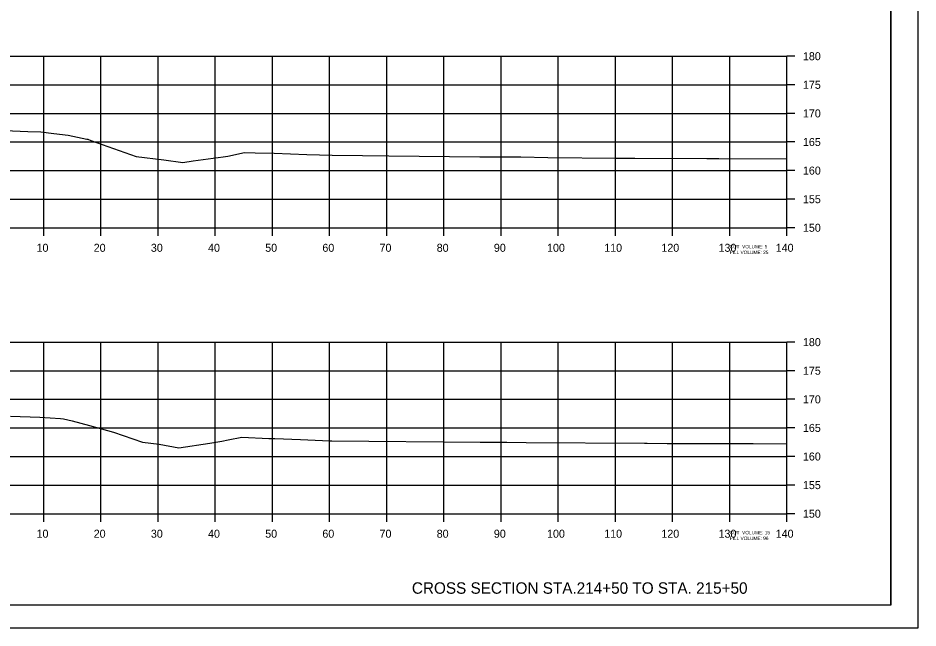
# Model space of a CAD drawing. Extents: x 1368503 to 1373085, y 379840 to 381833.
# Drawn here: x 1368678.6 to 1368836, y 381406.1 to 381512.7 of the extents above; entities that cross this region are included whole.
import ezdxf

# ---------------------------------------------------------------- set-up
doc = ezdxf.new("R2010")
doc.units = 0
for name, color, linetype in [('S_BRIDGE', 7, 'Continuous'), ('S_EDGE_PAVEMENT', 7, 'Continuous'), ('S_MISC_BOUNDARY', 7, 'Continuous'), ('S_PHOTO_CENTERS', 7, 'Continuous'), ('S_PHOTO_NOTES', 7, 'Continuous'), ('S_TRAILS', 7, 'Continuous'), ('S_TREE', 7, 'Continuous')]:
    doc.layers.add(name, color=color, linetype=linetype)

msp = doc.modelspace()

# ---------------------------------------------------------------- linework, layer by layer
at = {"layer": 'S_BRIDGE'}
for q in [(1368831.24, 381615.52), (1368515.06, 381410.06)]:
    msp.add_line((1368831.24, 381410.06), q, dxfattribs=at)
at = {"layer": 'S_EDGE_PAVEMENT'}
for p, q in [((1368813.06, 381476.06), (1368813.06, 381506.06)), ((1368814.46, 381506.06), (1368813.06, 381506.06)), ((1368814.46, 381501.06), (1368813.06, 381501.06)), ((1368814.46, 381496.06), (1368813.06, 381496.06)), ((1368814.46, 381491.06), (1368813.06, 381491.06)), ((1368814.46, 381486.06), (1368813.06, 381486.06)), ((1368814.46, 381481.06), (1368813.06, 381481.06)), ((1368533.06, 381476.06), (1368813.06, 381476.06)), ((1368683.06, 381474.66), (1368683.06, 381476.06)), ((1368693.06, 381474.66), (1368693.06, 381476.06)), ((1368703.06, 381474.66), (1368703.06, 381476.06)), ((1368713.06, 381474.66), (1368713.06, 381476.06)), ((1368723.06, 381474.66), (1368723.06, 381476.06)), ((1368733.06, 381474.66), (1368733.06, 381476.06)), ((1368743.06, 381474.66), (1368743.06, 381476.06)), ((1368753.06, 381474.66), (1368753.06, 381476.06)), ((1368763.06, 381474.66), (1368763.06, 381476.06)), ((1368773.06, 381474.66), (1368773.06, 381476.06)), ((1368783.06, 381474.66), (1368783.06, 381476.06)), ((1368793.06, 381474.66), (1368793.06, 381476.06)), ((1368803.06, 381474.66), (1368803.06, 381476.06)), ((1368813.06, 381474.66), (1368813.06, 381476.06)), ((1368814.46, 381476.06), (1368813.06, 381476.06)), ((1368813.06, 381426.06), (1368813.06, 381456.06)), ((1368814.46, 381456.06), (1368813.06, 381456.06)), ((1368814.46, 381451.06), (1368813.06, 381451.06)), ((1368814.46, 381446.06), (1368813.06, 381446.06)), ((1368814.46, 381441.06), (1368813.06, 381441.06)), ((1368814.46, 381436.06), (1368813.06, 381436.06)), ((1368814.46, 381431.06), (1368813.06, 381431.06)), ((1368533.06, 381426.06), (1368813.06, 381426.06)), ((1368683.06, 381424.66), (1368683.06, 381426.06)), ((1368693.06, 381424.66), (1368693.06, 381426.06)), ((1368703.06, 381424.66), (1368703.06, 381426.06)), ((1368713.06, 381424.66), (1368713.06, 381426.06)), ((1368723.06, 381424.66), (1368723.06, 381426.06)), ((1368733.06, 381424.66), (1368733.06, 381426.06)), ((1368743.06, 381424.66), (1368743.06, 381426.06)), ((1368753.06, 381424.66), (1368753.06, 381426.06)), ((1368763.06, 381424.66), (1368763.06, 381426.06)), ((1368773.06, 381424.66), (1368773.06, 381426.06)), ((1368783.06, 381424.66), (1368783.06, 381426.06)), ((1368793.06, 381424.66), (1368793.06, 381426.06)), ((1368803.06, 381424.66), (1368803.06, 381426.06)), ((1368813.06, 381424.66), (1368813.06, 381426.06)), ((1368814.46, 381426.06), (1368813.06, 381426.06))]:
    msp.add_line(p, q, dxfattribs=at)
at = {"layer": 'S_MISC_BOUNDARY'}
for points in [[(1368673.59, 381493.17), (1368680.27, 381492.92), (1368682.58, 381492.84), (1368684.85, 381492.57), (1368687.33, 381492.26), (1368690.59, 381491.56), (1368690.77, 381491.53), (1368691.32, 381491.32), (1368699.22, 381488.5), (1368704.08, 381487.93), (1368707.41, 381487.5), (1368709.22, 381487.78), (1368714.47, 381488.47), (1368715.29, 381488.61), (1368718.16, 381489.22), (1368720.07, 381489.16), (1368723.35, 381489.11), (1368729.06, 381488.88), (1368733.52, 381488.75), (1368738.83, 381488.68), (1368743.42, 381488.62), (1368759.35, 381488.44), (1368766.52, 381488.44), (1368771.25, 381488.37), (1368783.17, 381488.22), (1368786.48, 381488.21), (1368799.04, 381488.2), (1368801.14, 381488.19), (1368813.06, 381488.14)], [(1368677.23, 381443.09), (1368682.36, 381442.92), (1368685.99, 381442.69), (1368686.53, 381442.66), (1368688.01, 381442.28), (1368691.07, 381441.47), (1368695.29, 381440.31), (1368700.32, 381438.59), (1368703.27, 381438.24), (1368706.69, 381437.58), (1368712.12, 381438.41), (1368713.54, 381438.63), (1368714.2, 381438.75), (1368715.32, 381438.96), (1368717.72, 381439.43), (1368722.43, 381439.23), (1368723.49, 381439.19), (1368727.98, 381439.01), (1368733.09, 381438.79), (1368733.45, 381438.78), (1368759.4, 381438.56), (1368764.07, 381438.55), (1368767.46, 381438.5), (1368788.14, 381438.38), (1368788.62, 381438.38), (1368792.1, 381438.36), (1368804.56, 381438.32), (1368807.15, 381438.31), (1368813.06, 381438.28)]]:
    msp.add_lwpolyline(points, dxfattribs=at)
at = {"layer": 'S_PHOTO_CENTERS'}
for p, q in [((1368533.06, 381506.06), (1368813.06, 381506.06)), ((1368683.06, 381476.06), (1368683.06, 381506.06)), ((1368693.06, 381476.06), (1368693.06, 381506.06)), ((1368703.06, 381476.06), (1368703.06, 381506.06)), ((1368713.06, 381476.06), (1368713.06, 381506.06)), ((1368723.06, 381476.06), (1368723.06, 381506.06)), ((1368733.06, 381476.06), (1368733.06, 381506.06)), ((1368743.06, 381476.06), (1368743.06, 381506.06)), ((1368753.06, 381476.06), (1368753.06, 381506.06)), ((1368763.06, 381476.06), (1368763.06, 381506.06)), ((1368773.06, 381476.06), (1368773.06, 381506.06)), ((1368783.06, 381476.06), (1368783.06, 381506.06)), ((1368793.06, 381476.06), (1368793.06, 381506.06)), ((1368803.06, 381476.06), (1368803.06, 381506.06)), ((1368813.06, 381476.06), (1368813.06, 381506.06)), ((1368533.06, 381501.06), (1368813.06, 381501.06)), ((1368533.06, 381496.06), (1368813.06, 381496.06)), ((1368533.06, 381491.06), (1368813.06, 381491.06)), ((1368533.06, 381486.06), (1368813.06, 381486.06)), ((1368533.06, 381481.06), (1368813.06, 381481.06)), ((1368533.06, 381476.06), (1368813.06, 381476.06)), ((1368533.06, 381456.06), (1368813.06, 381456.06)), ((1368683.06, 381426.06), (1368683.06, 381456.06)), ((1368693.06, 381426.06), (1368693.06, 381456.06)), ((1368703.06, 381426.06), (1368703.06, 381456.06)), ((1368713.06, 381426.06), (1368713.06, 381456.06)), ((1368723.06, 381426.06), (1368723.06, 381456.06)), ((1368733.06, 381426.06), (1368733.06, 381456.06)), ((1368743.06, 381426.06), (1368743.06, 381456.06)), ((1368753.06, 381426.06), (1368753.06, 381456.06)), ((1368763.06, 381426.06), (1368763.06, 381456.06)), ((1368773.06, 381426.06), (1368773.06, 381456.06)), ((1368783.06, 381426.06), (1368783.06, 381456.06)), ((1368793.06, 381426.06), (1368793.06, 381456.06)), ((1368803.06, 381426.06), (1368803.06, 381456.06)), ((1368813.06, 381426.06), (1368813.06, 381456.06)), ((1368533.06, 381451.06), (1368813.06, 381451.06)), ((1368533.06, 381446.06), (1368813.06, 381446.06)), ((1368533.06, 381441.06), (1368813.06, 381441.06)), ((1368533.06, 381436.06), (1368813.06, 381436.06)), ((1368533.06, 381431.06), (1368813.06, 381431.06)), ((1368533.06, 381426.06), (1368813.06, 381426.06))]:
    msp.add_line(p, q, dxfattribs=at)
at = {"layer": 'S_PHOTO_NOTES'}
msp.add_line((1368502.66, 381406.08), (1368835.99, 381406.08), dxfattribs=at)
for points in [[(1368502.65, 381619.41), (1368835.99, 381619.41), (1368835.99, 381406.07), (1368502.65, 381406.07)], [(1368748.98, 381615.52), (1368748.98, 381605.64), (1368784.71, 381605.64), (1368784.71, 381602.72), (1368807.91, 381602.72), (1368807.91, 381578.38), (1368831.24, 381578.38), (1368831.24, 381410.06), (1368515.06, 381410.06), (1368515.06, 381615.52)]]:
    msp.add_lwpolyline(points, close=True, dxfattribs=at)

# ---------------------------------------------------------------- texts
at = {"layer": 'S_TRAILS'}
for s, height, p in [('180', 1.4, (1368815.86, 381505.36)), ('175', 1.4, (1368815.86, 381500.36)), ('170', 1.4, (1368815.86, 381495.36)), ('165', 1.4, (1368815.86, 381490.36)), ('160', 1.4, (1368815.86, 381485.36)), ('155', 1.4, (1368815.86, 381480.36)), ('150', 1.4, (1368815.86, 381475.36)), ('10', 1.4, (1368681.8, 381471.86)), ('20', 1.4, (1368691.8, 381471.86)), ('30', 1.4, (1368701.8, 381471.86)), ('40', 1.4, (1368711.8, 381471.86)), ('50', 1.4, (1368721.8, 381471.86)), ('60', 1.4, (1368731.8, 381471.86)), ('70', 1.4, (1368741.8, 381471.86)), ('80', 1.4, (1368751.8, 381471.86)), ('90', 1.4, (1368761.8, 381471.86)), ('100', 1.4, (1368771.1, 381471.86)), ('110', 1.4, (1368781.1, 381471.86)), ('120', 1.4, (1368791.1, 381471.86)), ('130', 1.4, (1368801.1, 381471.86)), ('CUT  VOLUME: 5', 0.6, (1368803.06, 381472.46)), ('140', 1.4, (1368811.1, 381471.86)), ('FILL VOLUME: 25', 0.6, (1368803.06, 381471.46)), ('180', 1.4, (1368815.86, 381455.36)), ('175', 1.4, (1368815.86, 381450.36)), ('170', 1.4, (1368815.86, 381445.36)), ('165', 1.4, (1368815.86, 381440.36)), ('160', 1.4, (1368815.86, 381435.36)), ('155', 1.4, (1368815.86, 381430.36)), ('150', 1.4, (1368815.86, 381425.36)), ('10', 1.4, (1368681.8, 381421.86)), ('20', 1.4, (1368691.8, 381421.86)), ('30', 1.4, (1368701.8, 381421.86)), ('40', 1.4, (1368711.8, 381421.86)), ('50', 1.4, (1368721.8, 381421.86)), ('60', 1.4, (1368731.8, 381421.86)), ('70', 1.4, (1368741.8, 381421.86)), ('80', 1.4, (1368751.8, 381421.86)), ('90', 1.4, (1368761.8, 381421.86)), ('100', 1.4, (1368771.1, 381421.86)), ('110', 1.4, (1368781.1, 381421.86)), ('120', 1.4, (1368791.1, 381421.86)), ('130', 1.4, (1368801.1, 381421.86)), ('CUT  VOLUME: 15', 0.6, (1368803.06, 381422.46)), ('140', 1.4, (1368811.1, 381421.86)), ('FILL VOLUME: 96', 0.6, (1368803.06, 381421.46))]:
    msp.add_text(s, height=height, dxfattribs=at).set_placement(p)
at = {"layer": 'S_TREE'}
msp.add_text('CROSS SECTION STA.214+50 TO STA. 215+50', height=2, dxfattribs=at).set_placement((1368747.46, 381412.06))

doc.saveas('drawing.dxf')
